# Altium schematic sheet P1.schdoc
size 420 x 297 mm; Symbol: Drawing-Symbol_A4; Company: 嘉立创EDA; Version: V1.0; Page Size: A4; @Project Name: NE555 Modulator (10 chips); @Update Date: 2026-01-12; @Create Date: 2026-01-12; Device: Drawing-Symbol_A4; @Board Name: Board1; @Page Name: P1; @Create Time: 15:54:46; @Page Count: 1; @Page No: 1; @Schematic Name: Schematic1; @Update Time: 15:54:46; @Assembly Variant: Basic; Border: 1; Title Block Position: 3; Size: A4; Width: 1655; Height: 1170; Region Start: 1; X Region Count: 6; Y Region Count: 4; Blade Width: 10; Title Block: 1
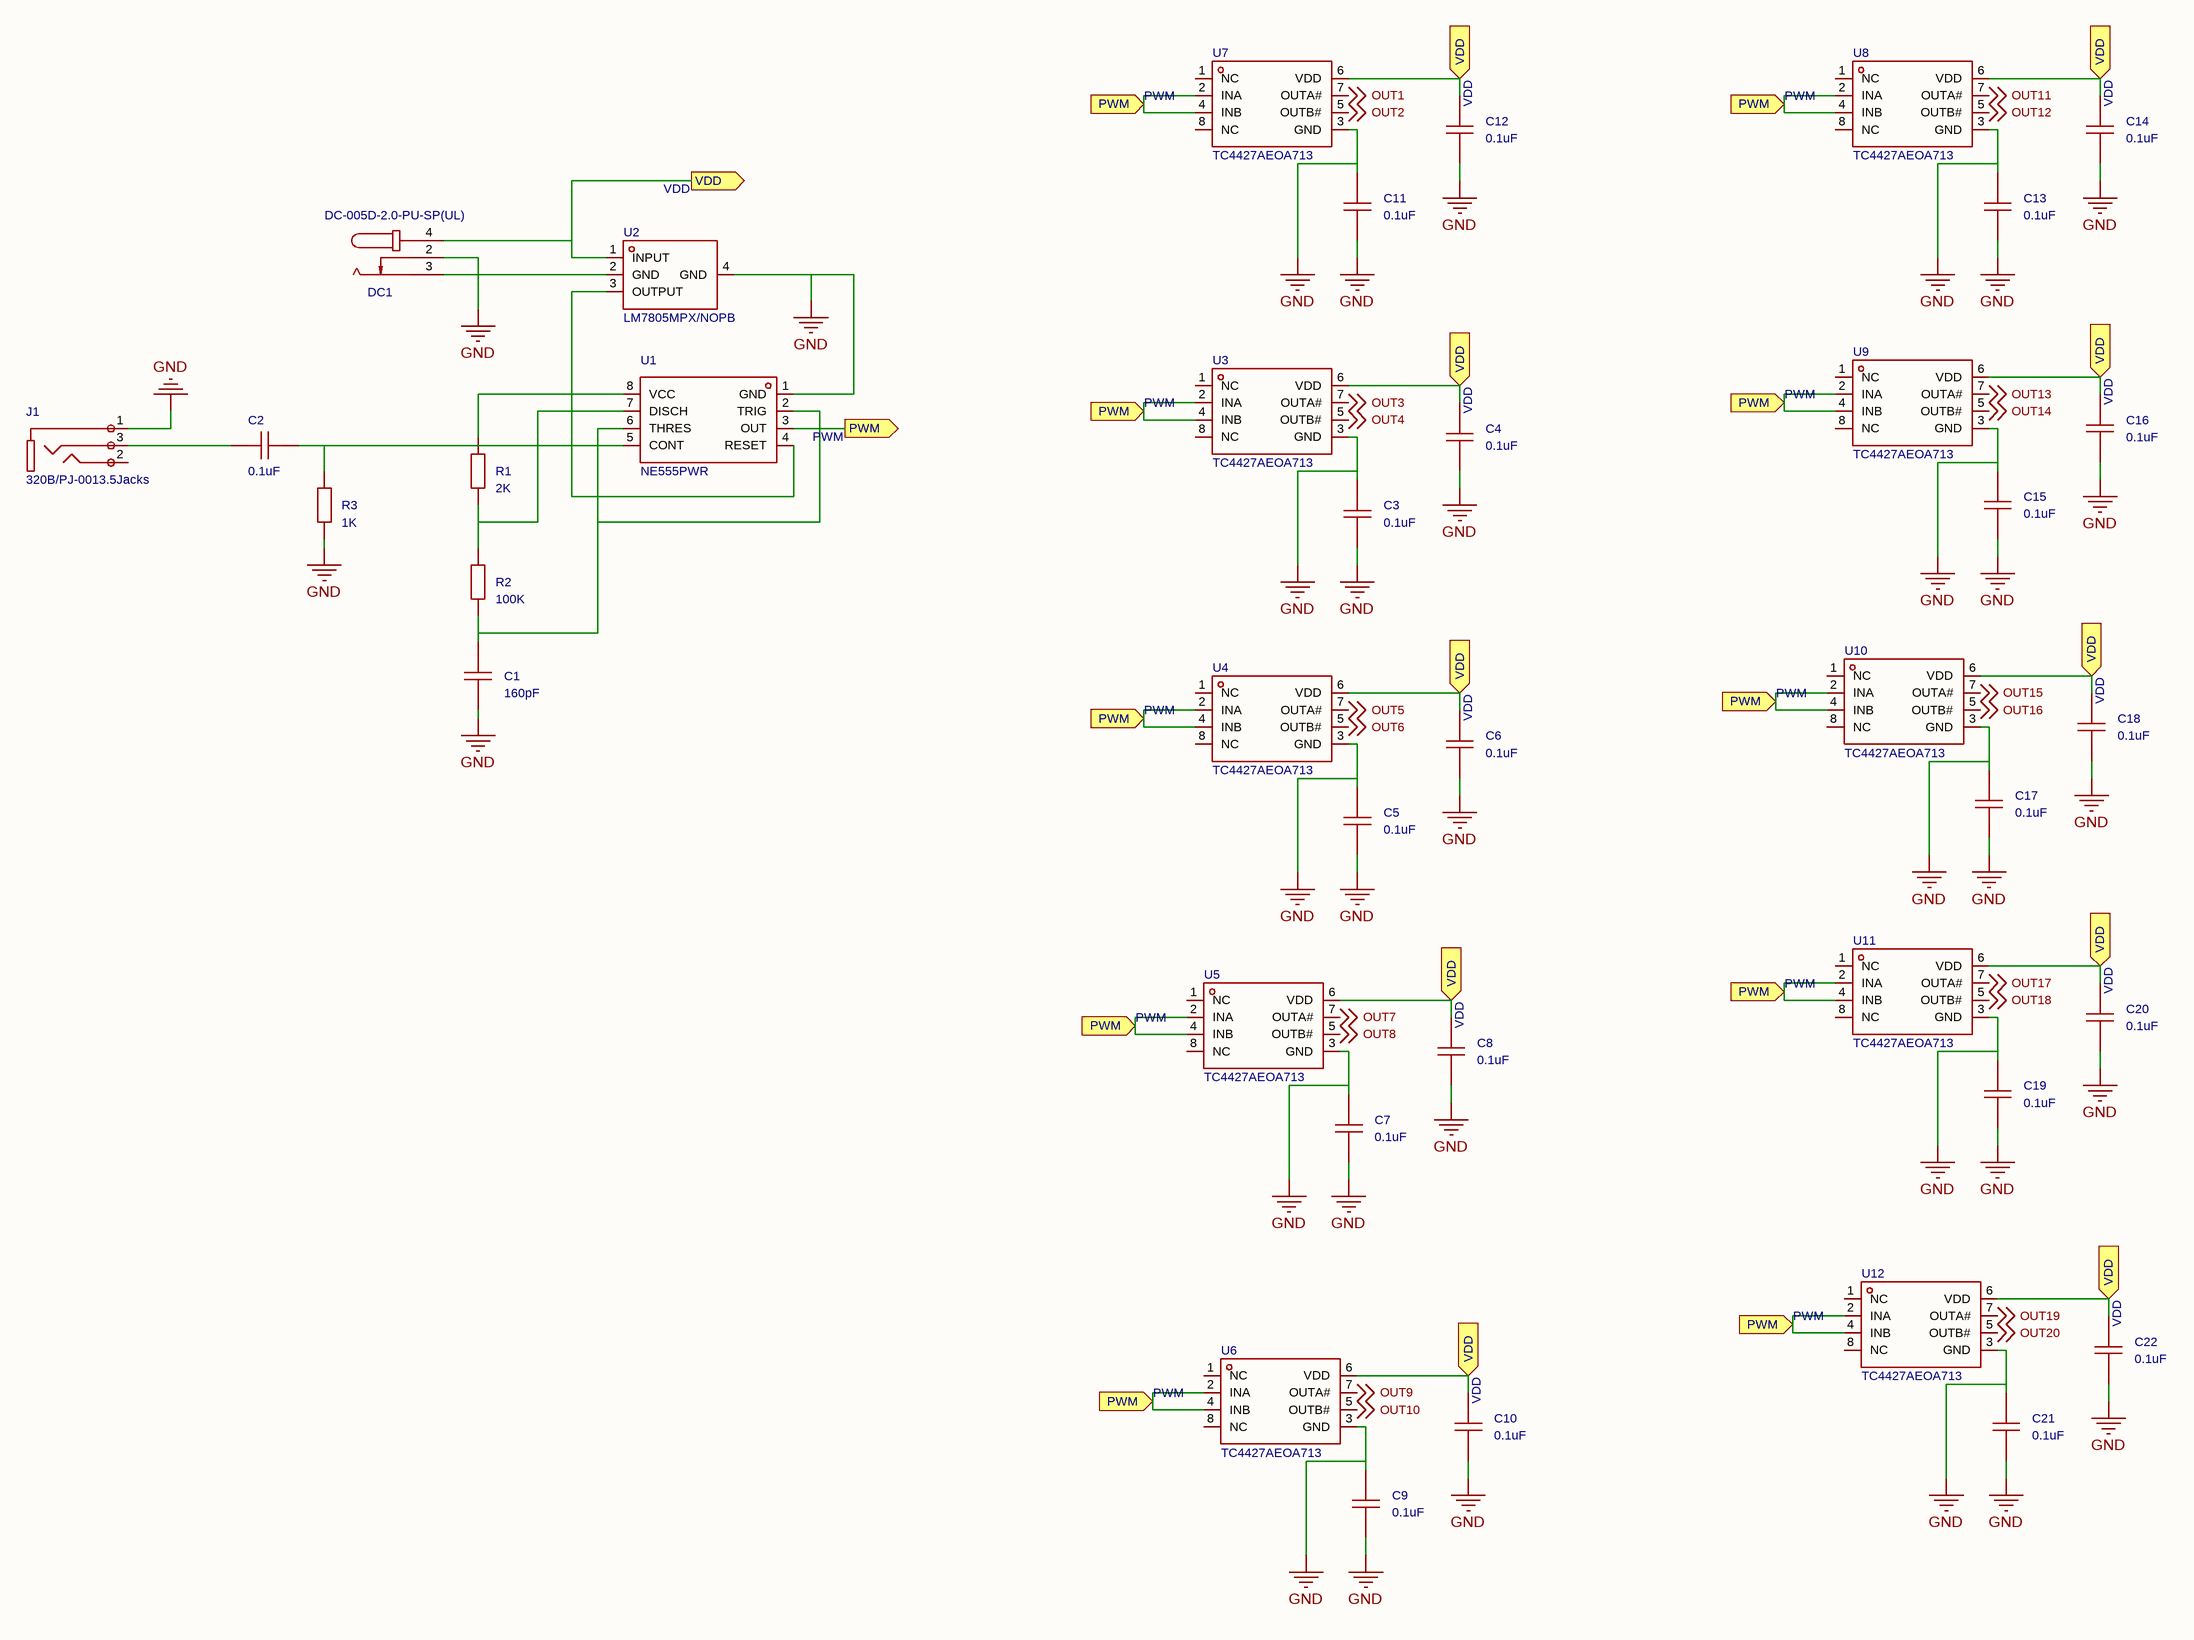
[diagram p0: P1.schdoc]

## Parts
C1  160pF  [C0603]
C2  0.1uF  [C0603]
C3  0.1uF  [C0603]
C4  0.1uF  [C0603]
C5  0.1uF  [C0603]
C6  0.1uF  [C0603]
C7  0.1uF  [C0603]
C8  0.1uF  [C0603]
C9  0.1uF  [C0603]
C10  0.1uF  [C0603]
C11  0.1uF  [C0603]
C12  0.1uF  [C0603]
C13  0.1uF  [C0603]
C14  0.1uF  [C0603]
C15  0.1uF  [C0603]
C16  0.1uF  [C0603]
C17  0.1uF  [C0603]
C18  0.1uF  [C0603]
C19  0.1uF  [C0603]
C20  0.1uF  [C0603]
C21  0.1uF  [C0603]
C22  0.1uF  [C0603]
DC1  DC-005D-2.0-PU-SP(UL)  [DC-IN-TH_DC-005D-2.0-PU-SP]
J1  320B/PJ-0013.5Jacks  [AUDIO-SMD_PJ-320B]
R1  2K  [R0603]
R2  100K  [R0603]
R3  1K  [R0603]
U1  NE555PWR  [TSSOP-8_L4.4-W3.0-P0.65-LS6.4-BL]
U2  LM7805MPX/NOPB  [SOT-223-4_L6.5-W3.5-P2.30-LS7.0-BR]
U3  TC4427AEOA713  [SOIC-8_L4.9-W3.9-P1.27-LS6.0-BL]
U4  TC4427AEOA713  [SOIC-8_L4.9-W3.9-P1.27-LS6.0-BL]
U5  TC4427AEOA713  [SOIC-8_L4.9-W3.9-P1.27-LS6.0-BL]
U6  TC4427AEOA713  [SOIC-8_L4.9-W3.9-P1.27-LS6.0-BL]
U7  TC4427AEOA713  [SOIC-8_L4.9-W3.9-P1.27-LS6.0-BL]
U8  TC4427AEOA713  [SOIC-8_L4.9-W3.9-P1.27-LS6.0-BL]
U9  TC4427AEOA713  [SOIC-8_L4.9-W3.9-P1.27-LS6.0-BL]
U10  TC4427AEOA713  [SOIC-8_L4.9-W3.9-P1.27-LS6.0-BL]
U11  TC4427AEOA713  [SOIC-8_L4.9-W3.9-P1.27-LS6.0-BL]
U12  TC4427AEOA713  [SOIC-8_L4.9-W3.9-P1.27-LS6.0-BL]

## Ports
PWM (in), PWM (out), VDD (in), VDD (out)

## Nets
GND: C1.2 C3.1 C3.2 C4.1 C5.1 C5.2 C6.1 C7.1 C7.2 C8.1 C9.1 C9.2 C10.1 C11.1 C11.2 C12.1 C13.1 C13.2 C14.1 C15.1 C15.2 C16.1 C17.1 C17.2 C18.1 C19.1 C19.2 C20.1 C21.1 C21.2 C22.1 DC1.2 DC1.3 J1.1 R3.2 U1.1(GND) U2.2(GND) U2.4(GND) U3.3(GND) U4.3(GND) U5.3(GND) U6.3(GND) U7.3(GND) U8.3(GND) U9.3(GND) U10.3(GND) U11.3(GND) U12.3(GND)
OUT1: U7.7(OUTA#) ; off-sheet OUT1
OUT2: U7.5(OUTB#) ; off-sheet OUT2
OUT3: U3.7(OUTA#) ; off-sheet OUT3
OUT4: U3.5(OUTB#) ; off-sheet OUT4
OUT5: U4.7(OUTA#) ; off-sheet OUT5
OUT6: U4.5(OUTB#) ; off-sheet OUT6
OUT7: U5.7(OUTA#) ; off-sheet OUT7
OUT8: U5.5(OUTB#) ; off-sheet OUT8
OUT9: U6.7(OUTA#) ; off-sheet OUT9
OUT10: U6.5(OUTB#) ; off-sheet OUT10
OUT11: U8.7(OUTA#) ; off-sheet OUT11
OUT12: U8.5(OUTB#) ; off-sheet OUT12
OUT13: U9.7(OUTA#) ; off-sheet OUT13
OUT14: U9.5(OUTB#) ; off-sheet OUT14
OUT15: U10.7(OUTA#) ; off-sheet OUT15
OUT16: U10.5(OUTB#) ; off-sheet OUT16
OUT17: U11.7(OUTA#) ; off-sheet OUT17
OUT18: U11.5(OUTB#) ; off-sheet OUT18
OUT19: U12.7(OUTA#) ; off-sheet OUT19
OUT20: U12.5(OUTB#) ; off-sheet OUT20
PWM: C1.1 R2.2 U1.2(TRIG) U1.3(OUT) U1.6(THRES) U3.2(INA) U3.4(INB) U4.2(INA) U4.4(INB) U5.2(INA) U5.4(INB) U6.2(INA) U6.4(INB) U7.2(INA) U7.4(INB) U8.2(INA) U8.4(INB) U9.2(INA) U9.4(INB) U10.2(INA) U10.4(INB) U11.2(INA) U11.4(INB) U12.2(INA) U12.4(INB) ; port PWM
VDD: C4.2 C6.2 C8.2 C10.2 C12.2 C14.2 C16.2 C18.2 C20.2 C22.2 DC1.4 U2.1(INPUT) U3.6(VDD) U4.6(VDD) U5.6(VDD) U6.6(VDD) U7.6(VDD) U8.6(VDD) U9.6(VDD) U10.6(VDD) U11.6(VDD) U12.6(VDD) ; port VDD
NetC2_1: C2.1 J1.3
NetC2_2: C2.2 R3.1 U1.5(CONT)
NetR1_1: R1.1 U1.4(RESET) U1.8(VCC) U2.3(OUTPUT)
NetR1_2: R1.2 R2.1 U1.7(DISCH)

Not connected (* = marked no-connect by the designer): J1 2; U3 1(NC) 8(NC); U4 1(NC) 8(NC); U5 1(NC) 8(NC); U6 1(NC) 8(NC); U7 1(NC) 8(NC); U8 1(NC) 8(NC); U9 1(NC) 8(NC); U10 1(NC) 8(NC); U11 1(NC) 8(NC); U12 1(NC) 8(NC)

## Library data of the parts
C1 C2 = CAP_0603: Symbol: CapAcitance_1; 3D Model: ac125912035d415993ca9572d50418b1; 3D Model Transform: 62.992,31.496,0,0,0,0,0,0,0; ConvertToPcb: yes; ModelName: C0603_L1.6-W0.8-H0.8
C3-C22 = CAP_0603: Symbol: Capacitance; 3D Model: ac125912035d415993ca9572d50418b1; 3D Model Transform: 62.992,31.496,0,0,0,0,0,0,0; ConvertToPcb: yes; ModelName: C0603_L1.6-W0.8-H0.8
DC1 = DC-005D-2.0-PU-SP(UL): 连接器类型:DC电源插座;触点内径:2mm;触点外径:6.4mm;额定电流:5A;额定电压:48V;; Manufacturer: HOOYA(皓宇电子); 3D Model: cc42efdfad4c45a4b3fc0e7b10bbaf9b; 3D Model Transform: 562.991,370.078,0,0,0,0,-136.811,84.645,-161.417; Connector Type: DC电源插座; Inside Contact Diameter: 2mm; Outside Contact Diameter: 6.4mm; Current Rating (Max): 5A; Voltage Rating (Max): 48V; AddInBom: yes
J1 = 320B/PJ-0013.5Jacks: 3D Model: 3d47e225fd634a229e5ea035a81040be; 3D Model Transform: 354.33,551.18,0,0,0,0,0,62.992,-19.685; AddInBom: yes; ModelName: AUDIO-PJ320B_L14.0-W6.4-H4.0
R1-R3 = Res_0603: Symbol: 电阻; 3D Model: fc143cca1e79419f9cd78b61e9279f08; 3D Model Transform: 31.8897,63.7794,0,90,0,0,0,0,0; ConvertToPcb: yes
U1 = NE555PWR: NE555 单精度定时器; Manufacturer: TI(德州仪器); 3D Model: 2d0fd2703afb4f81a9dfc54e2181a624; 3D Model Transform: 118.11,251.968,0,0,0,0,0,0,0; AddInBom: yes; ModelName: TSSOP-8_L4.4-W3.0-P0.65-LS6.4-BL-2
U2 = LM7805MPX/NOPB: 输出类型:固定;工作电压:25V;输出电压:5V;输出电流:1.5A;电源纹波抑制比(PSRR):62dB@(120Hz);输出极性:正极;; Manufacturer: TI(德州仪器); 3D Model: 925194bf9823436183a3e0b978a8d076; 3D Model Transform: 279.89794,255.905,0,180,0,0,-0.0005,-0.0005,0; Output Type: 固定; Voltage - Supply: 25V; Output Voltage: 5V; Output Current: 1.5A; Voltage Dropout: 2V@(1A); standby current: 8mA; Noise: 40uV; Output Configuration: 正极; Number of Outputs: 1; AddInBom: yes; ModelName: SOT-223-4P_L6.5-W3.5-H1.6-LS7.0-P2.30
U3-U12 = TC4427AEOA713_C5804606: 驱动配置:低边;负载类型:MOSFET;灌电流(IOL):-;拉电流(IOH):-;工作电压:4.5V~20V;; Manufacturer: JSMSEMI(杰盛微); 3D Model: e81d2f7d937b4a6ab1dca543ff5d56a4; 3D Model Transform: 189.751,236.22,0,0,0,0,0.0005,0.0005,0; Driven Configuration: 低边; Load Type: MOSFET; AddInBom: yes; ModelName: SOIC-8_L4.9-W3.9-H1.7-LS6.0-P1.27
